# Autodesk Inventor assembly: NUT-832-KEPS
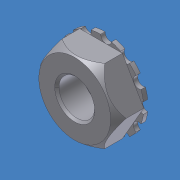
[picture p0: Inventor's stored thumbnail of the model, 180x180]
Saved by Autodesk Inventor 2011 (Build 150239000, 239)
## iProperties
Created: 2007-09
Part Number: NUT-832-KEPS
Document SubType Name: Assembly
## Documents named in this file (3)
- C:\Data Folder\VEX 2011\Inventor Datasets\Unit 16\Components\NUT-832-KEPS.iam
- C:\Data Folder\VEX 2011\Inventor Datasets\Unit 16\Components\8-32 KEPS NUT-1.ipt
- C:\Data Folder\VEX 2011\Inventor Datasets\Unit 16\Components\8-32 KEPS NUT-2.ipt
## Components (2 placed, 2 different names)
1. 8-32 KEPS NUT-1:1 — Insert:1
2. 8-32 KEPS NUT-2:1 — Insert:1
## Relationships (1: Insert 1)
- Insert:1: 8-32 KEPS NUT-1:1 ↔ 8-32 KEPS NUT-2:1
